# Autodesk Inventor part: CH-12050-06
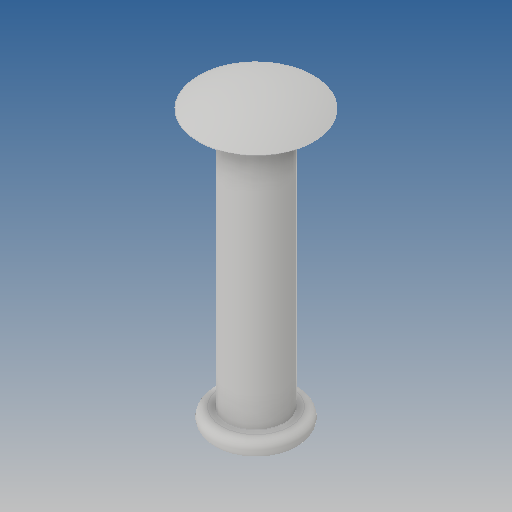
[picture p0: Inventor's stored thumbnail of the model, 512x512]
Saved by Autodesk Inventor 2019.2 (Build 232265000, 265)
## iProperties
Created: 2015-08
Part Number: CH-12050-06
Material: Ogólny
Document SubType Name: Modeling
Designer: CADENGINEERING4
Density: 1 g/cm^3
Appearance: Domyślna
Author: CADENGINEERING4
Revision Number: ÈÎºÎ
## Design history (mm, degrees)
feature "Ô²½Ç2"
node "Bryła1"
